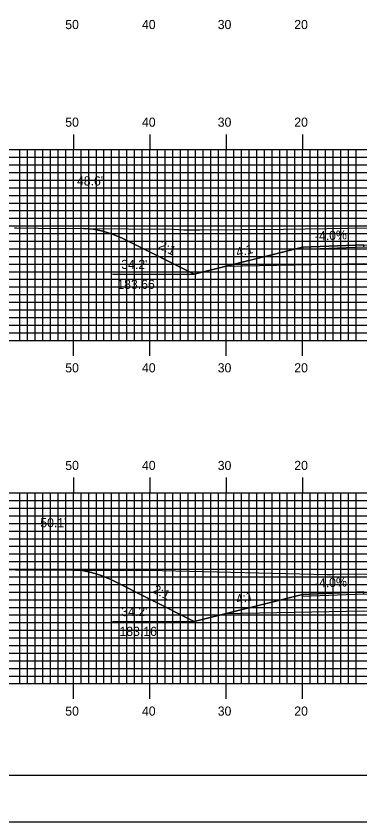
# Model space of a CAD drawing. Extents: x 1797994 to 1798337, y 442591 to 442811.
# Drawn here: x 1798102.5 to 1798147.5, y 442590.5 to 442696.2 of the extents above; entities that cross this region are included whole.
import ezdxf

# ---------------------------------------------------------------- set-up
doc = ezdxf.new("R2010")
doc.units = 0
for name, color, linetype in [('ANNOTATION', 7, 'Continuous'), ('BORDER', 7, 'Continuous'), ('D_Roadway_Centerline', 7, 'Continuous'), ('D_Roadway_Edge_Shoulder', 7, 'Continuous'), ('D_Roadway_SlopeLines', 7, 'Continuous'), ('D_Roadway_SubGrade', 7, 'Continuous'), ('D_Text_Standard', 7, 'Continuous'), ('H_V ANNOTATION', 7, 'Continuous'), ('MAJOR', 7, 'Continuous'), ('MINOR', 7, 'Continuous'), ('PDRAIN', 7, 'Continuous'), ('PLOT BOUNDARY', 7, 'Continuous'), ('S_Roadway_Centerline', 7, 'Continuous')]:
    doc.layers.add(name, color=color, linetype=linetype)

msp = doc.modelspace()

# ---------------------------------------------------------------- linework, layer by layer
at = {"layer": 'BORDER'}
msp.add_lwpolyline([(1798010.36, 442596.67), (1798330.36, 442596.67), (1798330.36, 442806.67), (1798010.36, 442806.67)], close=True, dxfattribs=at)
at = {"layer": 'D_Roadway_Centerline'}
for points in [[(1798111.32, 442668.33), (1798112.57, 442668.24), (1798113.82, 442668), (1798115.07, 442667.61), (1798116.32, 442667.06), (1798125.78, 442662.33), (1798129.78, 442663.33), (1798139.96, 442665.87), (1798147.96, 442666.19), (1798159.96, 442665.95), (1798171.96, 442665.71), (1798179.96, 442665.39), (1798190.13, 442662.85), (1798194.13, 442661.85), (1798202.71, 442666.13), (1798203.96, 442666.67), (1798205.21, 442667.05), (1798206.46, 442667.25), (1798207.71, 442667.28)], [(1798109.84, 442623.56), (1798111.09, 442623.48), (1798112.34, 442623.24), (1798113.59, 442622.85), (1798114.84, 442622.3), (1798125.78, 442616.83), (1798129.78, 442617.83), (1798139.96, 442620.37), (1798147.96, 442620.69), (1798159.96, 442620.45), (1798171.96, 442620.21), (1798179.96, 442619.89), (1798190.13, 442617.35), (1798194.13, 442616.35), (1798204.11, 442621.33), (1798205.36, 442621.88), (1798206.61, 442622.28), (1798207.86, 442622.52), (1798209.11, 442622.61)]]:
    msp.add_lwpolyline(points, dxfattribs=at)
at = {"layer": 'D_Roadway_Edge_Shoulder'}
for points in [[(1798147.96, 442666.19), (1798139.96, 442665.87), (1798139.96, 442665.62), (1798147.96, 442665.94)], [(1798147.96, 442620.69), (1798139.96, 442620.37), (1798139.96, 442620.12), (1798147.96, 442620.44)]]:
    msp.add_lwpolyline(points, close=True, dxfattribs=at)
at = {"layer": 'D_Roadway_SlopeLines'}
for points in [[(1798125.78, 442662.33), (1798116.32, 442667.06), (1798115.07, 442667.61), (1798113.82, 442668), (1798112.57, 442668.24), (1798111.32, 442668.33)], [(1798139.96, 442665.87), (1798125.78, 442662.33)], [(1798125.78, 442616.83), (1798114.84, 442622.3), (1798113.59, 442622.85), (1798112.34, 442623.24), (1798111.09, 442623.48), (1798109.84, 442623.56)], [(1798139.96, 442620.37), (1798125.78, 442616.83)]]:
    msp.add_lwpolyline(points, dxfattribs=at)
at = {"layer": 'D_Roadway_SubGrade'}
for points in [[(1798147.96, 442663.69), (1798129.78, 442663.33), (1798139.96, 442665.87), (1798139.96, 442665.62), (1798147.96, 442665.94), (1798159.96, 442665.7), (1798171.96, 442665.46), (1798179.96, 442665.14), (1798179.96, 442665.39), (1798190.13, 442662.85), (1798171.96, 442663.21), (1798159.96, 442663.45)], [(1798147.96, 442618.19), (1798129.78, 442617.83), (1798139.96, 442620.37), (1798139.96, 442620.12), (1798147.96, 442620.44), (1798159.96, 442620.2), (1798171.96, 442619.96), (1798179.96, 442619.64), (1798179.96, 442619.89), (1798190.13, 442617.35), (1798171.96, 442617.71), (1798159.96, 442617.95)]]:
    msp.add_lwpolyline(points, close=True, dxfattribs=at)
at = {"layer": 'MAJOR'}
for p, q in [((1798109.96, 442680.67), (1798109.96, 442678.67)), ((1798119.96, 442680.67), (1798119.96, 442678.67)), ((1798129.96, 442680.67), (1798129.96, 442678.67)), ((1798139.96, 442680.67), (1798139.96, 442678.67)), ((1798019.96, 442678.67), (1798299.96, 442678.67)), ((1798019.96, 442678.67), (1798299.96, 442678.67)), ((1798109.96, 442653.67), (1798109.96, 442678.67)), ((1798119.96, 442653.67), (1798119.96, 442678.67)), ((1798129.96, 442653.67), (1798129.96, 442678.67)), ((1798139.96, 442653.67), (1798139.96, 442678.67)), ((1798019.96, 442673.67), (1798299.96, 442673.67)), ((1798019.96, 442668.67), (1798299.96, 442668.67)), ((1798019.96, 442663.67), (1798299.96, 442663.67)), ((1798019.96, 442658.67), (1798299.96, 442658.67)), ((1798019.96, 442653.67), (1798299.96, 442653.67)), ((1798019.96, 442653.67), (1798299.96, 442653.67)), ((1798109.96, 442651.66), (1798109.96, 442653.67)), ((1798119.96, 442651.66), (1798119.96, 442653.67)), ((1798129.96, 442651.66), (1798129.96, 442653.67)), ((1798139.96, 442651.66), (1798139.96, 442653.67)), ((1798109.96, 442635.67), (1798109.96, 442633.67)), ((1798119.96, 442635.67), (1798119.96, 442633.67)), ((1798129.96, 442635.67), (1798129.96, 442633.67)), ((1798139.96, 442635.67), (1798139.96, 442633.67)), ((1798019.96, 442633.67), (1798299.96, 442633.67)), ((1798019.96, 442633.67), (1798299.96, 442633.67)), ((1798109.96, 442608.67), (1798109.96, 442633.67)), ((1798119.96, 442608.67), (1798119.96, 442633.67)), ((1798129.96, 442608.67), (1798129.96, 442633.67)), ((1798139.96, 442608.67), (1798139.96, 442633.67)), ((1798019.96, 442628.67), (1798299.96, 442628.67)), ((1798019.96, 442623.67), (1798299.96, 442623.67)), ((1798019.96, 442618.67), (1798299.96, 442618.67)), ((1798019.96, 442613.67), (1798299.96, 442613.67)), ((1798019.96, 442608.67), (1798299.96, 442608.67)), ((1798019.96, 442608.67), (1798299.96, 442608.67)), ((1798109.96, 442606.66), (1798109.96, 442608.67)), ((1798119.96, 442606.66), (1798119.96, 442608.67)), ((1798129.96, 442606.66), (1798129.96, 442608.67)), ((1798139.96, 442606.66), (1798139.96, 442608.67))]:
    msp.add_line(p, q, dxfattribs=at)
at = {"layer": 'MINOR'}
for p, q in [((1798102.96, 442653.67), (1798102.96, 442678.67)), ((1798103.96, 442653.67), (1798103.96, 442678.67)), ((1798104.96, 442653.67), (1798104.96, 442678.67)), ((1798105.96, 442653.67), (1798105.96, 442678.67)), ((1798106.96, 442653.67), (1798106.96, 442678.67)), ((1798107.96, 442653.67), (1798107.96, 442678.67)), ((1798108.96, 442653.67), (1798108.96, 442678.67)), ((1798110.96, 442653.67), (1798110.96, 442678.67)), ((1798111.96, 442653.67), (1798111.96, 442678.67)), ((1798112.96, 442653.67), (1798112.96, 442678.67)), ((1798113.96, 442653.67), (1798113.96, 442678.67)), ((1798114.96, 442653.67), (1798114.96, 442678.67)), ((1798115.96, 442653.67), (1798115.96, 442678.67)), ((1798116.96, 442653.67), (1798116.96, 442678.67)), ((1798117.96, 442653.67), (1798117.96, 442678.67)), ((1798118.96, 442653.67), (1798118.96, 442678.67)), ((1798120.96, 442653.67), (1798120.96, 442678.67)), ((1798121.96, 442653.67), (1798121.96, 442678.67)), ((1798122.96, 442653.67), (1798122.96, 442678.67)), ((1798123.96, 442653.67), (1798123.96, 442678.67)), ((1798124.96, 442653.67), (1798124.96, 442678.67)), ((1798125.96, 442653.67), (1798125.96, 442678.67)), ((1798126.96, 442653.67), (1798126.96, 442678.67)), ((1798127.96, 442653.67), (1798127.96, 442678.67)), ((1798128.96, 442653.67), (1798128.96, 442678.67)), ((1798130.96, 442653.67), (1798130.96, 442678.67)), ((1798131.96, 442653.67), (1798131.96, 442678.67)), ((1798132.96, 442653.67), (1798132.96, 442678.67)), ((1798133.96, 442653.67), (1798133.96, 442678.67)), ((1798134.96, 442653.67), (1798134.96, 442678.67)), ((1798135.96, 442653.67), (1798135.96, 442678.67)), ((1798136.96, 442653.67), (1798136.96, 442678.67)), ((1798137.96, 442653.67), (1798137.96, 442678.67)), ((1798138.96, 442653.67), (1798138.96, 442678.67)), ((1798140.96, 442653.67), (1798140.96, 442678.67)), ((1798141.96, 442653.67), (1798141.96, 442678.67)), ((1798142.96, 442653.67), (1798142.96, 442678.67)), ((1798143.96, 442653.67), (1798143.96, 442678.67)), ((1798144.96, 442653.67), (1798144.96, 442678.67)), ((1798145.96, 442653.67), (1798145.96, 442678.67)), ((1798146.96, 442653.67), (1798146.96, 442678.67)), ((1798019.96, 442677.67), (1798299.96, 442677.67)), ((1798019.96, 442676.67), (1798299.96, 442676.67)), ((1798019.96, 442675.67), (1798299.96, 442675.67)), ((1798019.96, 442674.67), (1798299.96, 442674.67)), ((1798019.96, 442672.67), (1798299.96, 442672.67)), ((1798019.96, 442671.67), (1798299.96, 442671.67)), ((1798019.96, 442670.67), (1798299.96, 442670.67)), ((1798019.96, 442669.67), (1798299.96, 442669.67)), ((1798019.96, 442667.67), (1798299.96, 442667.67)), ((1798019.96, 442666.67), (1798299.96, 442666.67)), ((1798019.96, 442665.67), (1798299.96, 442665.67)), ((1798019.96, 442664.67), (1798299.96, 442664.67)), ((1798019.96, 442662.67), (1798299.96, 442662.67)), ((1798019.96, 442661.67), (1798299.96, 442661.67)), ((1798019.96, 442660.67), (1798299.96, 442660.67)), ((1798019.96, 442659.67), (1798299.96, 442659.67)), ((1798019.96, 442657.67), (1798299.96, 442657.67)), ((1798019.96, 442656.67), (1798299.96, 442656.67)), ((1798019.96, 442655.67), (1798299.96, 442655.67)), ((1798019.96, 442654.67), (1798299.96, 442654.67)), ((1798102.96, 442608.67), (1798102.96, 442633.67)), ((1798103.96, 442608.67), (1798103.96, 442633.67)), ((1798104.96, 442608.67), (1798104.96, 442633.67)), ((1798105.96, 442608.67), (1798105.96, 442633.67)), ((1798106.96, 442608.67), (1798106.96, 442633.67)), ((1798107.96, 442608.67), (1798107.96, 442633.67)), ((1798108.96, 442608.67), (1798108.96, 442633.67)), ((1798110.96, 442608.67), (1798110.96, 442633.67)), ((1798111.96, 442608.67), (1798111.96, 442633.67)), ((1798112.96, 442608.67), (1798112.96, 442633.67)), ((1798113.96, 442608.67), (1798113.96, 442633.67)), ((1798114.96, 442608.67), (1798114.96, 442633.67)), ((1798115.96, 442608.67), (1798115.96, 442633.67)), ((1798116.96, 442608.67), (1798116.96, 442633.67)), ((1798117.96, 442608.67), (1798117.96, 442633.67)), ((1798118.96, 442608.67), (1798118.96, 442633.67)), ((1798120.96, 442608.67), (1798120.96, 442633.67)), ((1798121.96, 442608.67), (1798121.96, 442633.67)), ((1798122.96, 442608.67), (1798122.96, 442633.67)), ((1798123.96, 442608.67), (1798123.96, 442633.67)), ((1798124.96, 442608.67), (1798124.96, 442633.67)), ((1798125.96, 442608.67), (1798125.96, 442633.67)), ((1798126.96, 442608.67), (1798126.96, 442633.67)), ((1798127.96, 442608.67), (1798127.96, 442633.67)), ((1798128.96, 442608.67), (1798128.96, 442633.67)), ((1798130.96, 442608.67), (1798130.96, 442633.67)), ((1798131.96, 442608.67), (1798131.96, 442633.67)), ((1798132.96, 442608.67), (1798132.96, 442633.67)), ((1798133.96, 442608.67), (1798133.96, 442633.67)), ((1798134.96, 442608.67), (1798134.96, 442633.67)), ((1798135.96, 442608.67), (1798135.96, 442633.67)), ((1798136.96, 442608.67), (1798136.96, 442633.67)), ((1798137.96, 442608.67), (1798137.96, 442633.67)), ((1798138.96, 442608.67), (1798138.96, 442633.67)), ((1798140.96, 442608.67), (1798140.96, 442633.67)), ((1798141.96, 442608.67), (1798141.96, 442633.67)), ((1798142.96, 442608.67), (1798142.96, 442633.67)), ((1798143.96, 442608.67), (1798143.96, 442633.67)), ((1798144.96, 442608.67), (1798144.96, 442633.67)), ((1798145.96, 442608.67), (1798145.96, 442633.67)), ((1798146.96, 442608.67), (1798146.96, 442633.67)), ((1798019.96, 442632.67), (1798299.96, 442632.67)), ((1798019.96, 442631.67), (1798299.96, 442631.67)), ((1798019.96, 442630.67), (1798299.96, 442630.67)), ((1798019.96, 442629.67), (1798299.96, 442629.67)), ((1798019.96, 442627.67), (1798299.96, 442627.67)), ((1798019.96, 442626.67), (1798299.96, 442626.67)), ((1798019.96, 442625.67), (1798299.96, 442625.67)), ((1798019.96, 442624.67), (1798299.96, 442624.67)), ((1798019.96, 442622.67), (1798299.96, 442622.67)), ((1798019.96, 442621.67), (1798299.96, 442621.67)), ((1798019.96, 442620.67), (1798299.96, 442620.67)), ((1798019.96, 442619.67), (1798299.96, 442619.67)), ((1798019.96, 442617.67), (1798299.96, 442617.67)), ((1798019.96, 442616.67), (1798299.96, 442616.67)), ((1798019.96, 442615.67), (1798299.96, 442615.67)), ((1798019.96, 442614.67), (1798299.96, 442614.67)), ((1798019.96, 442612.67), (1798299.96, 442612.67)), ((1798019.96, 442611.67), (1798299.96, 442611.67)), ((1798019.96, 442610.67), (1798299.96, 442610.67)), ((1798019.96, 442609.67), (1798299.96, 442609.67))]:
    msp.add_line(p, q, dxfattribs=at)
at = {"layer": 'PDRAIN'}
for p, q in [((1798115.06, 442662.33), (1798125.78, 442662.33)), ((1798115.06, 442616.83), (1798125.78, 442616.83))]:
    msp.add_line(p, q, dxfattribs=at)
at = {"layer": 'PLOT BOUNDARY'}
msp.add_lwpolyline([(1797994.17, 442590.55), (1798334.17, 442590.55), (1798334.17, 442810.55), (1797994.17, 442810.55)], close=True, dxfattribs=at)
at = {"layer": 'S_Roadway_Centerline'}
for points in [[(1798102.25, 442668.41), (1798102.51, 442668.41), (1798105.32, 442668.38), (1798123.11, 442668.23), (1798124.43, 442668.16), (1798126.54, 442668.15), (1798137.46, 442668.24), (1798145.98, 442668.37), (1798148.44, 442668.4), (1798151.99, 442668.21), (1798160.37, 442667.79), (1798166.3, 442668.04), (1798178.7, 442668.14), (1798183.51, 442667.97), (1798187.61, 442668), (1798203.6, 442667.45), (1798210.16, 442667.18), (1798218.97, 442667.3)], [(1798019.96, 442624.18), (1798026.96, 442624.23), (1798036.73, 442624.33), (1798039.99, 442624.27), (1798059.51, 442623.72), (1798061.88, 442623.71), (1798065.3, 442623.74), (1798080.87, 442623.7), (1798092, 442623.71), (1798102.39, 442623.6), (1798118.19, 442623.52), (1798120.17, 442623.54), (1798121.59, 442623.48), (1798143.17, 442622.99), (1798143.68, 442622.99), (1798144.17, 442623), (1798155.33, 442623.07), (1798165.69, 442622.78), (1798179.35, 442622.67), (1798186.61, 442622.56), (1798195.7, 442622.49), (1798202.28, 442622.51), (1798207.69, 442622.6), (1798213.43, 442622.63)]]:
    msp.add_lwpolyline(points, dxfattribs=at)

# ---------------------------------------------------------------- texts
at = {"layer": 'ANNOTATION'}
for s, rotation, p in [('-4.0%', 2.2906, (1798141.59, 442666.74)), ('2:1', 333.4349, (1798120.99, 442665.76)), ('4:1', 14.0362, (1798131.41, 442664.59)), ('-4.0%', 2.2906, (1798141.59, 442621.24)), ('2:1', 333.4349, (1798120.24, 442620.63)), ('4:1', 14.0362, (1798131.41, 442619.09))]:
    msp.add_text(s, height=1.2, rotation=rotation, dxfattribs=at).set_placement(p)
for s, p in [("34.2'", (1798116.22, 442663.02)), ('183.66', (1798115.7, 442660.42)), ("34.2'", (1798116.22, 442617.52)), ('183.16', (1798115.98, 442614.92))]:
    msp.add_text(s, height=1.2, dxfattribs=at).set_placement(p)
at = {"layer": 'D_Text_Standard'}
for s, p in [("48.6'", (1798110.42, 442673.97)), ("50.1'", (1798105.62, 442629.17))]:
    msp.add_text(s, height=1.2, dxfattribs=at).set_placement(p)
at = {"layer": 'H_V ANNOTATION'}
for s, p in [('50', (1798108.89, 442694.47)), ('40', (1798118.93, 442694.47)), ('30', (1798128.85, 442694.47)), ('20', (1798138.87, 442694.47)), ('50', (1798108.89, 442681.67)), ('40', (1798118.93, 442681.67)), ('30', (1798128.85, 442681.67)), ('20', (1798138.87, 442681.67)), ('50', (1798108.89, 442649.47)), ('40', (1798118.93, 442649.47)), ('30', (1798128.85, 442649.47)), ('20', (1798138.87, 442649.47)), ('50', (1798108.89, 442636.67)), ('40', (1798118.93, 442636.67)), ('30', (1798128.85, 442636.67)), ('20', (1798138.87, 442636.67)), ('50', (1798108.89, 442604.47)), ('40', (1798118.93, 442604.47)), ('30', (1798128.85, 442604.47)), ('20', (1798138.87, 442604.47))]:
    msp.add_text(s, height=1.2, dxfattribs=at).set_placement(p)

doc.saveas('drawing.dxf')
